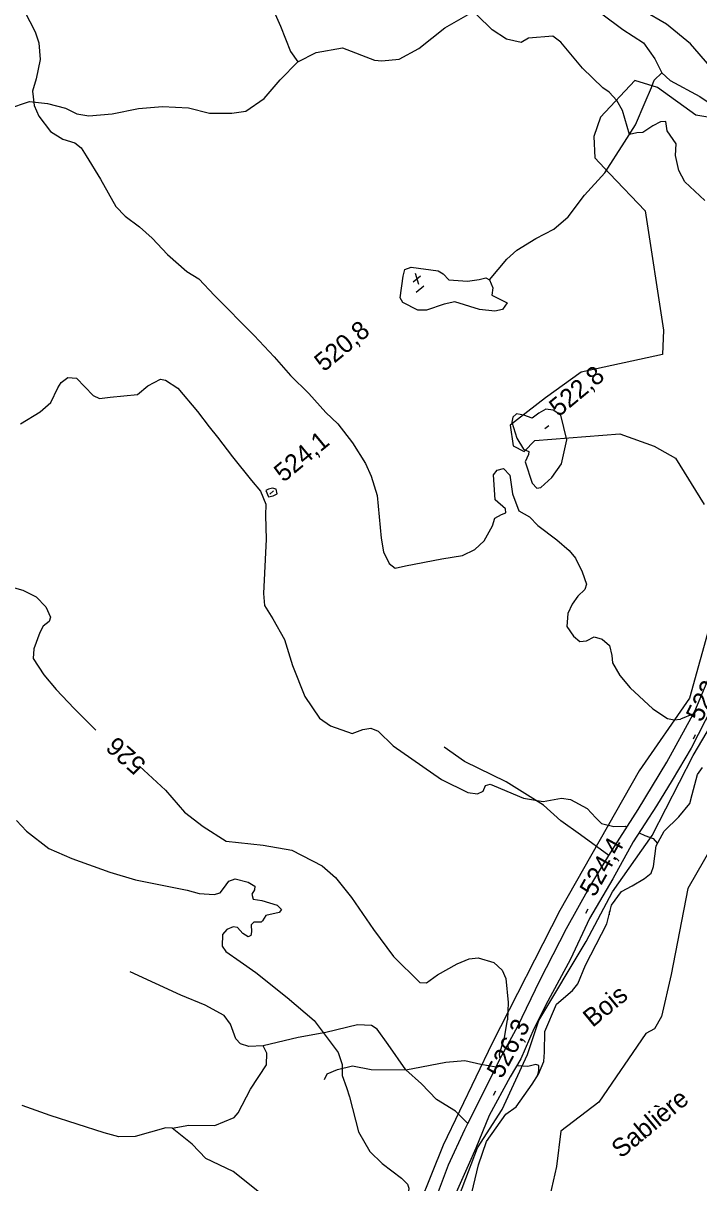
# Model space of a CAD drawing. Extents: x 347059 to 352153, y 6073752 to 6078601.
# Drawn here: x 347423 to 347588.7, y 6075388.2 to 6075672.7 of the extents above; entities that cross this region are included whole.
import ezdxf

# ---------------------------------------------------------------- set-up
doc = ezdxf.new("R2010")
doc.units = 0
for name, color, linetype in [('Level 1', 7, 'Continuous'), ('Level 19', 7, 'Continuous'), ('Level 2', 7, 'Continuous'), ('Level 22', 7, 'Continuous'), ('Level 3', 7, 'Continuous'), ('Level 4', 7, 'Continuous'), ('Level 44', 7, 'Continuous'), ('Level 54', 7, 'Continuous')]:
    doc.layers.add(name, color=color, linetype=linetype)

msp = doc.modelspace()

# ---------------------------------------------------------------- linework, layer by layer
at = {"layer": 'Level 1'}
for points in [[(347566.65, 6075655.76), (347565.14, 6075656.79), (347560.15, 6075661.61), (347554.8, 6075668.01), (347552.88, 6075669.49), (347546.94, 6075668.98), (347545.14, 6075667.89), (347541.47, 6075668.72), (347538.01, 6075671.06), (347530.54, 6075678.37)], [(347621.59, 6075639.38), (347619.79, 6075637.08), (347618.18, 6075636.14), (347616.52, 6075635.78), (347615, 6075636.13), (347612.98, 6075638.48), (347610.61, 6075642.8), (347609.41, 6075646.47), (347607.27, 6075649.48), (347602.77, 6075651.52), (347597.98, 6075654.96), (347595.1, 6075657.94), (347591.34, 6075662.13), (347586.61, 6075667.6), (347580.78, 6075672.43), (347575.07, 6075675.7)], [(347590.17, 6075629.13), (347585.22, 6075633.73), (347583.79, 6075636.52), (347582.93, 6075640.24), (347583.13, 6075643.08), (347580.95, 6075646.24), (347580.58, 6075648.51), (347579.24, 6075648.48), (347577.42, 6075647.52), (347574.98, 6075645.87), (347573.47, 6075645.78), (347571.65, 6075645.38), (347569.96, 6075651.28), (347568.59, 6075653.66), (347566.65, 6075655.76)]]:
    msp.add_lwpolyline(points, dxfattribs=at)
at = {"layer": 'Level 19'}
for points in [[(347523.81, 6075383.42), (347527.31, 6075392.63), (347531.3, 6075401.28), (347532.06, 6075402.77), (347535.32, 6075409.2), (347538.94, 6075416.65), (347539.85, 6075418.54), (347544.29, 6075426.59), (347549.65, 6075437.86), (347556.25, 6075450.59), (347561.76, 6075460.55), (347566.62, 6075468.46), (347567.98, 6075470.68), (347573.83, 6075479.81), (347580.81, 6075491.42), (347587.68, 6075503.86), (347593.13, 6075516.73)], [(347591.94, 6075504.86), (347586.83, 6075494.84), (347582.11, 6075486.99), (347578.33, 6075480.7), (347572.61, 6075471.84), (347567.57, 6075462.8), (347561.9, 6075453), (347557.17, 6075443.1), (347551.67, 6075432.76), (347548.17, 6075425.97), (347545, 6075418.63), (347542.37, 6075414.17), (347537.23, 6075404.75), (347533.97, 6075396.73), (347532.08, 6075392.46), (347529.16, 6075385.8)]]:
    msp.add_lwpolyline(points, dxfattribs=at)
at = {"layer": 'Level 2'}
for points in [[(347423.27, 6075675.58), (347425.87, 6075670.54), (347426.79, 6075667.84), (347427.13, 6075663.72), (347426.1, 6075659), (347425.23, 6075656.01), (347425.62, 6075652.47), (347426.76, 6075649.82), (347429.63, 6075646.07), (347432.68, 6075644.2)], [(347432.68, 6075644.2), (347435.59, 6075643.29), (347437.16, 6075642.06), (347438.37, 6075640.13), (347441.93, 6075634.42), (347445.69, 6075627.67), (347447.95, 6075625.29), (347451.45, 6075622.72), (347454.62, 6075619.89), (347458.35, 6075615.91), (347463.09, 6075611.71), (347466, 6075609.99), (347469.86, 6075605.86), (347479.57, 6075596.04), (347484.5, 6075590.79), (347488.54, 6075586.27), (347493.04, 6075581.86), (347497.22, 6075577.19), (347500.11, 6075574.38)], [(347422.28, 6075574.39), (347427.09, 6075577.32), (347429.72, 6075579.63), (347431.45, 6075583.2), (347432.23, 6075584.51), (347433.89, 6075585.75), (347436.07, 6075585.56), (347440.13, 6075581.35), (347441.67, 6075580.63), (347444.26, 6075580.91), (347450.98, 6075581.56), (347453.52, 6075583.67), (347456.6, 6075585.3), (347457.83, 6075585.12), (347460.86, 6075583.1), (347465.74, 6075577.43)], [(347465.74, 6075577.43), (347468.61, 6075573.68), (347470.63, 6075571.1), (347474.27, 6075566.26), (347478.99, 6075560.45), (347481.16, 6075557.85), (347482.47, 6075554.68), (347482.36, 6075551.92), (347482.53, 6075546.07), (347481.93, 6075532.79), (347482.16, 6075529.78), (347484.19, 6075526.54), (347487.08, 6075521.47), (347489.04, 6075515.1), (347492.05, 6075507.48), (347495.65, 6075502.2), (347498.33, 6075500.29), (347503.65, 6075498.43), (347506.23, 6075499.37), (347508.24, 6075499.7), (347510.01, 6075499.03), (347513.7, 6075495.43), (347525.6, 6075487.15), (347532.04, 6075483.95), (347534.36, 6075483.6), (347535.82, 6075484.27), (347536.39, 6075485.68), (347537.52, 6075485.95), (347538.51, 6075485.57), (347545.71, 6075482.59), (347550.47, 6075481.73), (347555.03, 6075482.57), (347557.2, 6075482.23), (347561.32, 6075480.04), (347563.38, 6075477.74), (347564.79, 6075476.38), (347567.87, 6075475.59), (347570.68, 6075475.7), (347571.08, 6075475.51)], [(347546.05, 6075565.09), (347547.81, 6075559.8), (347548.91, 6075558.62), (347549.89, 6075558.79), (347552.63, 6075561.23), (347554.99, 6075564.55), (347556.31, 6075570.46), (347554.8, 6075576.5), (347552.94, 6075577.77), (347551.13, 6075577.95), (347549.47, 6075576.98), (347547.84, 6075575.8), (347545.74, 6075576.48), (347543.98, 6075576.86), (347543.02, 6075576.03), (347542.85, 6075574.75), (347544.03, 6075570.84), (347545.7, 6075568.2), (347547, 6075567.58), (347546.91, 6075566.89), (347546.05, 6075565.09)], [(347500.11, 6075574.38), (347503.71, 6075569.76), (347506.89, 6075564.66), (347508.28, 6075561.54), (347509.82, 6075556.8), (347510.73, 6075546.35), (347511.37, 6075543.01), (347512.71, 6075540.12), (347514.21, 6075538.96), (347516.69, 6075539.55), (347525.67, 6075541.24), (347530.75, 6075542.11), (347533.75, 6075543.53), (347536.01, 6075545.67), (347538.05, 6075549.36), (347538.67, 6075551.2), (347540.29, 6075552.14), (347541.33, 6075552.51), (347541.24, 6075553.49), (347538.76, 6075555.74), (347538.35, 6075561.83), (347539.21, 6075563.02), (347540.78, 6075563.39), (347542.33, 6075561.77), (347542.97, 6075557.18), (347544.57, 6075553.02), (347547.15, 6075551.55), (347549.16, 6075549.48), (347553.89, 6075545.92), (347556.88, 6075543.32), (347558.47, 6075541.42), (347560.06, 6075538.07), (347561.09, 6075535.05), (347560.68, 6075533.78), (347558.97, 6075532.1), (347557.61, 6075530.17), (347556.58, 6075527.85), (347556.28, 6075524.66), (347557.97, 6075522.32), (347559.46, 6075521.02), (347561.09, 6075521.17), (347563.02, 6075522.1), (347564.95, 6075521.56), (347566.79, 6075520.01), (347567.37, 6075517.55), (347567.49, 6075515.78), (347569.32, 6075512.62), (347571.83, 6075509.62), (347577.37, 6075504.46), (347580.97, 6075502.09), (347582.63, 6075501.73), (347584.2, 6075501.95)], [(347482.48, 6075557.99), (347483.1, 6075556.49), (347484.29, 6075556.68), (347485.26, 6075557.22), (347484.98, 6075558.34), (347484.11, 6075558.64), (347483.12, 6075558.39), (347482.48, 6075557.99)], [(347407.26, 6075539.62), (347410.44, 6075537.74), (347415.21, 6075535.72), (347422.89, 6075533.59), (347426.17, 6075531.92), (347428.49, 6075529.46), (347429.64, 6075526.96), (347429.32, 6075525.9), (347427.89, 6075524.71), (347427.02, 6075523.19), (347425.54, 6075519.18), (347425.39, 6075516.79), (347428.01, 6075512.85), (347431.02, 6075509.24), (347435.47, 6075504.55), (347440.47, 6075499.53), (347440.81, 6075499.25)], [(347587.36, 6075503.27), (347584.2, 6075501.95)], [(347451.5, 6075490.42), (347457.83, 6075484.53), (347462.5, 6075479.1), (347467.07, 6075475.57), (347472.72, 6075472.01), (347481.85, 6075471.05), (347488.82, 6075469.77), (347496.29, 6075465.98), (347499.52, 6075463.07), (347503.45, 6075458.21), (347508.85, 6075450.3), (347513.79, 6075443.75), (347520.21, 6075437.35), (347521.88, 6075437.27), (347524.56, 6075439.22), (347529.43, 6075441.91), (347532.33, 6075443.11), (347534.55, 6075443.35), (347538.4, 6075442.27), (347540.42, 6075440.35), (347541.32, 6075438.3), (347541.93, 6075432.42), (347541.74, 6075428.14)], [(347421.35, 6075477.07), (347423.79, 6075474.45), (347429.22, 6075470.2), (347434.9, 6075467.73), (347444.21, 6075464.43), (347450.52, 6075462.49), (347463.2, 6075459.98), (347466.12, 6075459.21), (347469.82, 6075458.95), (347471.24, 6075459.33), (347472.07, 6075460.42), (347473.41, 6075462.19), (347474.93, 6075462.78), (347478.14, 6075461.99), (347479.79, 6075460.97), (347479.71, 6075460.1), (347479.02, 6075459), (347479.35, 6075457.81), (347481.51, 6075457.47), (347485.27, 6075456.34), (347486.33, 6075455.23), (347485.75, 6075454.48), (347482.47, 6075453.75), (347481.69, 6075452.44), (347481.29, 6075452.12), (347479.54, 6075452.13), (347478.89, 6075451.46), (347478.95, 6075449.78), (347478.79, 6075448.85), (347478.1, 6075448.55), (347476.87, 6075449.39), (347475.54, 6075450.81), (347474.46, 6075450.98), (347472.87, 6075450.33), (347471.87, 6075449.11), (347471.75, 6075446.21), (347472.65, 6075444.97), (347476.21, 6075442.47), (347480.04, 6075439.81)], [(347574.05, 6075474.08), (347575.45, 6075473.41), (347577.44, 6075472.7), (347578.53, 6075471.47)], [(347566.9, 6075454.99), (347566.68, 6075454.61), (347566.65, 6075453.93)], [(347480.04, 6075439.81), (347487.71, 6075433.67), (347494.33, 6075427.99), (347500.23, 6075420.13), (347501.2, 6075417.21), (347501.16, 6075414.52), (347502.27, 6075411.59), (347503, 6075409.27), (347505.18, 6075400.72), (347508.01, 6075395.89), (347511.02, 6075392.93), (347515.72, 6075389.38), (347517.26, 6075387.86), (347517.53, 6075386.89), (347517.14, 6075383.51), (347516.49, 6075380.59), (347516.59, 6075377.75), (347516.31, 6075367.96), (347515.88, 6075361.1), (347515.04, 6075355.36), (347515.6, 6075353.2), (347517.02, 6075352.74)], [(347540.05, 6075418.89), (347539.88, 6075418.97), (347539.78, 6075419.87), (347541.04, 6075423.83), (347541.74, 6075428.14)], [(347549.12, 6075414.47), (347549.43, 6075415.73), (347549.47, 6075416.96), (347548.69, 6075417.25), (347546.74, 6075416.7), (347544.4, 6075416.86), (347544.05, 6075417.02)]]:
    msp.add_lwpolyline(points, dxfattribs=at)
at = {"layer": 'Level 22'}
for points in [[(347566.62, 6075468.46), (347559.68, 6075473.54), (347554.86, 6075477.02), (347550.6, 6075480.83), (347541.4, 6075486.58), (347531.2, 6075491.56), (347526.19, 6075495.1)], [(347532.06, 6075402.77), (347528.96, 6075405.75), (347524.35, 6075408.65), (347520.62, 6075412.44), (347516.84, 6075415.91), (347512.52, 6075422.13), (347509.76, 6075425.86), (347508.37, 6075426.77), (347504.94, 6075426.99), (347497.2, 6075425.06), (347490.43, 6075423.82), (347481.83, 6075421.83), (347478.3, 6075421.65), (347476.24, 6075422.29), (347475.12, 6075423.5), (347473.84, 6075427.08), (347472.26, 6075429.26), (347467.59, 6075431.79), (347461.63, 6075434.25), (347449.23, 6075439.98)], [(347459.49, 6075401.58), (347463.55, 6075402.37), (347469.98, 6075402.25), (347474.69, 6075404.21), (347475.7, 6075405.38), (347478.71, 6075411.14), (347482.67, 6075417.12), (347482.68, 6075419.99), (347481.83, 6075421.83)], [(347496.88, 6075413.55), (347497.51, 6075414.92), (347500.02, 6075416.03), (347503.72, 6075416.88), (347508.31, 6075416.02), (347516.84, 6075415.91), (347526.66, 6075417.81), (347531.3, 6075418.19), (347535.21, 6075417.33), (347538.94, 6075416.65)], [(347431.11, 6075373.16), (347441.95, 6075369.09), (347447.87, 6075367.27), (347456, 6075365.7), (347462.31, 6075366.93), (347466.58, 6075365.64), (347470.68, 6075362.55), (347474.04, 6075361.45), (347477.15, 6075361.42), (347479.16, 6075362.48), (347480.3, 6075365.87), (347481.32, 6075375.33), (347482.27, 6075383.99), (347480.91, 6075385.83), (347474.49, 6075391), (347467.72, 6075394.13), (347464.43, 6075397.69), (347459.49, 6075401.58), (347457.97, 6075401.69), (347450.41, 6075399.55), (347446.44, 6075399.44), (347442.84, 6075400.47), (347429.57, 6075404.69), (347422.71, 6075407.14)]]:
    msp.add_lwpolyline(points, dxfattribs=at)
at = {"layer": 'Level 3'}
for p, q in [((347518.62, 6075609.23), (347520.43, 6075610.72)), ((347519.08, 6075611.36), (347519.91, 6075608.61)), ((347519.34, 6075606.71), (347521.19, 6075608.24)), ((347550.94, 6075573.22), (347551.86, 6075573.99)), ((347483.46, 6075557.16), (347484.38, 6075557.93)), ((347587.36, 6075497.12), (347587.89, 6075498.19)), ((347560.95, 6075454.34), (347561.54, 6075455.39)), ((347538.29, 6075409.74), (347538.85, 6075410.8))]:
    msp.add_line(p, q, dxfattribs=at)
at = {"layer": 'Level 4'}
for points in [[(347419.19, 6075651.65), (347424.48, 6075653.41), (347428.92, 6075653), (347433.34, 6075651.82), (347436.12, 6075650.43), (347439.05, 6075649.93), (347444.82, 6075650.43), (347451.26, 6075651.74), (347457.14, 6075652.19), (347463.54, 6075651.88), (347468.69, 6075650.56), (347474.14, 6075650.56), (347477.6, 6075651.12), (347482.09, 6075654.15), (347485.96, 6075658.78), (347490.31, 6075663.21), (347494.79, 6075665.48), (347501.3, 6075666.62), (347509.13, 6075663.6), (347510.91, 6075663.46), (347515.17, 6075663.8), (347520, 6075666.44), (347526.38, 6075671.49), (347533.26, 6075675.45)], [(347484.75, 6075674.91), (347486.07, 6075671.89), (347488.51, 6075665.74), (347490.31, 6075663.21)], [(347564.85, 6075674.94), (347570.04, 6075671.13), (347575.09, 6075667.83), (347577.91, 6075663.95), (347579.61, 6075660.49), (347581.63, 6075658.59), (347588.95, 6075654.66), (347593.77, 6075651.41), (347598.3, 6075647.98), (347601.59, 6075644.32), (347605.46, 6075638.58), (347608.21, 6075635.2), (347610.32, 6075633.62), (347613.61, 6075631.54), (347617.91, 6075627.23), (347623.9, 6075621.58), (347630.35, 6075615.64), (347636.32, 6075610.43), (347641.73, 6075603.6), (347645.83, 6075600.49)], [(347537.36, 6075609.67), (347541.56, 6075614.8), (347544.07, 6075616.97), (347548.68, 6075619.88), (347553.15, 6075622.15), (347556.63, 6075625.14), (347560.64, 6075630.49), (347565.63, 6075635.93), (347570.45, 6075643.5), (347573.12, 6075647.69), (347575.52, 6075653.32), (347577.05, 6075656.91), (347577.74, 6075658.65), (347579.61, 6075660.49)], [(347518.15, 6075612.81), (347524.75, 6075611.91), (347526, 6075611.17), (347527.32, 6075609.73), (347531.93, 6075609.38), (347534.81, 6075609.82), (347536.42, 6075610.23), (347537.36, 6075609.67), (347538.16, 6075607.78), (347537.94, 6075605.93), (347541.63, 6075604.03), (347540.53, 6075602.4), (347538.67, 6075602.01), (347534.92, 6075602.41), (347528.8, 6075604.33), (347526.23, 6075603.71), (347521.89, 6075602.25), (347519.74, 6075602.29), (347516.09, 6075604.14), (347515.4, 6075605.29), (347516.16, 6075610.64), (347516.6, 6075612.23), (347518.15, 6075612.81)]]:
    msp.add_lwpolyline(points, dxfattribs=at)
at = {"layer": 'Level 44'}
for points in [[(347594.77, 6075648.98), (347587.94, 6075650.06), (347578.58, 6075656.85), (347573.01, 6075658.57), (347564.56, 6075649.61), (347562.91, 6075644.86), (347563.18, 6075639.65), (347566.8, 6075635.8), (347575.49, 6075626.63), (347580.03, 6075597.37), (347579.75, 6075591.38), (347559.85, 6075587.09), (347551.1, 6075580.75), (347542.41, 6075574.02), (347543.1, 6075569.01), (347545.84, 6075567.59), (347548.47, 6075570.32), (347569.3, 6075571.93), (347577.7, 6075568.87), (347582.93, 6075565.96), (347589.99, 6075554.63)], [(347593.87, 6075533.84), (347586.4, 6075507.09), (347574.08, 6075489.27), (347554.62, 6075454.97), (347538.01, 6075422.43), (347525.97, 6075397.4), (347517.26, 6075375.7)], [(347527.74, 6075379.4), (347534.43, 6075396.78), (347540.47, 6075406.21), (347546.63, 6075419.68), (347549.43, 6075427.98), (347561.05, 6075447.37), (347567.54, 6075459.61), (347577.22, 6075473.41), (347587.33, 6075493.01), (347597.14, 6075509.64)], [(347596.39, 6075478.48), (347585.95, 6075460.37), (347581.87, 6075439.3), (347579.51, 6075429.01), (347577.8, 6075425.98), (347575.7, 6075424.81), (347564.13, 6075408), (347554.82, 6075400.88), (347553.78, 6075392.24), (347550.91, 6075379.59)]]:
    msp.add_lwpolyline(points, dxfattribs=at)
at = {"layer": 'Level 54'}
msp.add_lwpolyline([(347532.58, 6075384), (347534.62, 6075392.63), (347536.62, 6075398.35), (347538.93, 6075401.7), (347541.32, 6075405.05), (347543.88, 6075406.8), (347547.81, 6075412.38), (347549.37, 6075414.86), (347550.69, 6075417.96), (347550.85, 6075420.22), (347550.9, 6075425.32), (347553.73, 6075432), (347557.71, 6075435.35), (347558.97, 6075437.04), (347560.88, 6075441.56), (347566.12, 6075451.75), (347567.23, 6075456.33), (347569.74, 6075459.63), (347572.36, 6075461.05), (347575.37, 6075462.82), (347576.96, 6075464.12), (347577.53, 6075465.82), (347578.18, 6075470.84), (347580.19, 6075474.46), (347583.77, 6075478.01), (347586.44, 6075481.22), (347587.05, 6075483.48), (347588.38, 6075488.34), (347589.6, 6075490.07)], dxfattribs=at)

# ---------------------------------------------------------------- texts
at = {"layer": 'Level 2'}
msp.add_text('526', height=4.5, rotation=138.4261, dxfattribs=at).set_placement((347453.38, 6075491.29))
at = {"layer": 'Level 3'}
for s, rotation, p in [('  520,8', 39.57, (347494.14, 6075584.86)), ('522,8', 39.62, (347554.3, 6075575.94)), ('524,1', 39.62, (347486.82, 6075559.88)), ('522,5', 63.7428, (347589.32, 6075500.97)), ('524,4', 60.7866, (347563.1, 6075458.09)), ('526,3', 62.0242, (347540.37, 6075413.53))]:
    msp.add_text(s, height=4.5, rotation=rotation, dxfattribs=at).set_placement(p)
at = {"layer": 'Level 44'}
msp.add_text('Bois', height=4.5, rotation=39.568, dxfattribs=at).set_placement((347562.62, 6075426.16))
at = {"layer": 'Level 54'}
msp.add_text('Sablière', height=4.5, rotation=39.568, dxfattribs=at).set_placement((347569.58, 6075394.04))

doc.saveas('drawing.dxf')
